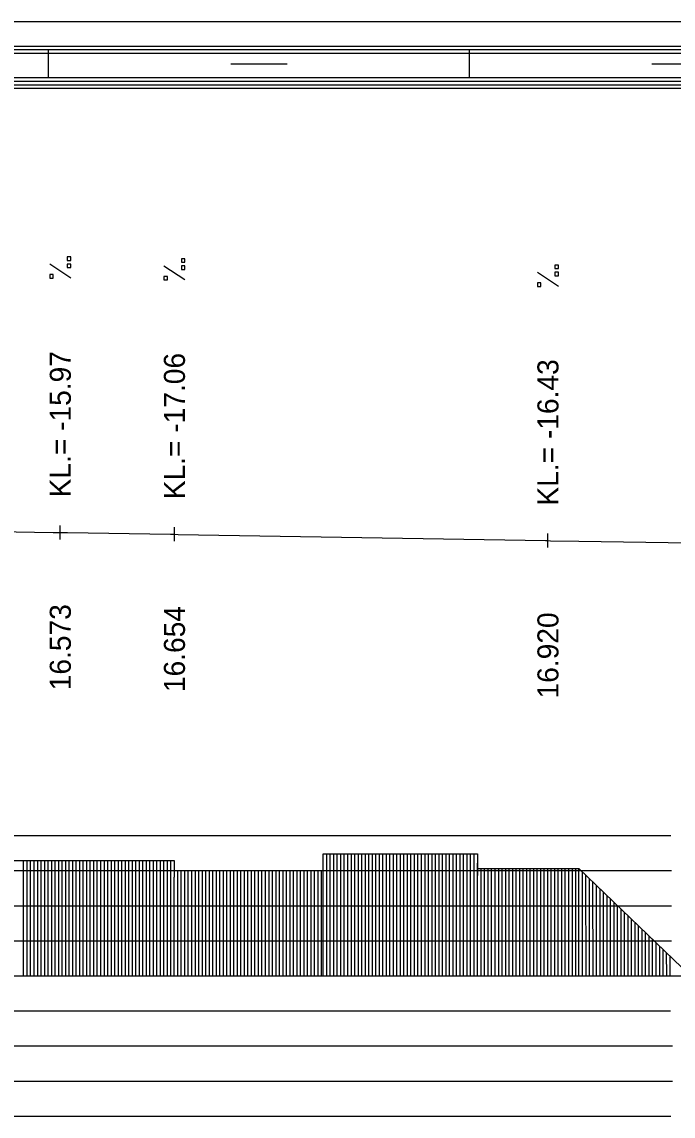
# Model space of a CAD drawing. Extents: x 2 to 10148, y 0 to 380.
# Drawn here: x 1953.1 to 1999.5, y 302 to 380 of the extents above; entities that cross this region are included whole.
import ezdxf

# ---------------------------------------------------------------- set-up
doc = ezdxf.new("R2010")
doc.units = 0
for name, color, linetype in [('NIVELETA_CARA', 7, 'Continuous'), ('NIVELETA_TEXT', 7, 'Continuous'), ('RAM', 7, 'Continuous'), ('ZRYCHL_CARA_C', 7, 'Continuous'), ('ZRYCHL_RASTR', 7, 'Continuous')]:
    doc.layers.add(name, color=color, linetype=linetype)

msp = doc.modelspace()

# ---------------------------------------------------------------- linework, layer by layer
at = {"layer": 'NIVELETA_CARA'}
for p, q in [((1955.842, 343.106), (1955.842, 344.106)), ((1947.82, 343.717), (1955.324, 343.613)), ((1955.324, 343.613), (1955.842, 343.606)), ((1955.842, 343.606), (1956.36, 343.598)), ((1956.36, 343.598), (1963.704, 343.48)), ((1963.704, 343.48), (1963.976, 343.476)), ((1963.976, 342.976), (1963.976, 343.976)), ((1963.976, 343.476), (1964.249, 343.471)), ((1964.249, 343.471), (1990.419, 343.025)), ((1990.593, 342.522), (1990.593, 343.522)), ((1990.419, 343.025), (1990.593, 343.022)), ((1990.593, 343.022), (1990.768, 343.019)), ((1990.768, 343.019), (1992.806, 342.986)), ((1992.806, 342.986), (2000.759, 342.856))]:
    msp.add_line(p, q, dxfattribs=at)
at = {"layer": 'NIVELETA_TEXT'}
for p, q in [((1956.589, 361.733), (1955.095, 362.724)), ((1956.59, 363.249), (1956.342, 363.249)), ((1956.342, 363.249), (1956.342, 363.006)), ((1956.342, 363.006), (1956.347, 363.002)), ((1956.342, 363.002), (1956.59, 363.002)), ((1956.59, 362.738), (1956.342, 362.738)), ((1956.342, 362.738), (1956.342, 362.495)), ((1956.59, 363.002), (1956.59, 363.249)), ((1956.59, 362.49), (1956.59, 362.738)), ((1964.724, 363.119), (1964.477, 363.119)), ((1964.477, 363.119), (1964.477, 362.876)), ((1964.477, 362.876), (1964.482, 362.872)), ((1964.477, 362.872), (1964.724, 362.872)), ((1964.724, 362.872), (1964.724, 363.119)), ((1955.342, 361.981), (1955.095, 361.981)), ((1955.095, 361.981), (1955.095, 361.738)), ((1955.342, 361.733), (1955.342, 361.981)), ((1956.342, 362.495), (1956.347, 362.49)), ((1956.342, 362.49), (1956.59, 362.49)), ((1964.723, 361.603), (1963.229, 362.594)), ((1964.724, 362.608), (1964.477, 362.608)), ((1964.477, 362.608), (1964.477, 362.365)), ((1964.477, 362.365), (1964.482, 362.36)), ((1964.477, 362.36), (1964.724, 362.36)), ((1964.724, 362.36), (1964.724, 362.608)), ((1991.34, 361.149), (1989.846, 362.14)), ((1991.341, 362.665), (1991.094, 362.665)), ((1991.094, 362.665), (1991.094, 362.422)), ((1991.094, 362.422), (1991.099, 362.418)), ((1991.094, 362.418), (1991.341, 362.418)), ((1991.341, 362.154), (1991.094, 362.154)), ((1991.094, 362.154), (1991.094, 361.911)), ((1991.341, 362.418), (1991.341, 362.665)), ((1991.341, 361.906), (1991.341, 362.154)), ((1955.095, 361.738), (1955.1, 361.733)), ((1955.095, 361.733), (1955.342, 361.733)), ((1963.477, 361.851), (1963.229, 361.851)), ((1963.229, 361.851), (1963.229, 361.608)), ((1963.229, 361.608), (1963.234, 361.603)), ((1963.229, 361.603), (1963.477, 361.603)), ((1963.477, 361.603), (1963.477, 361.851)), ((1990.094, 361.397), (1989.846, 361.397)), ((1989.846, 361.397), (1989.846, 361.154)), ((1989.846, 361.154), (1989.851, 361.149)), ((1989.846, 361.149), (1990.094, 361.149)), ((1990.094, 361.149), (1990.094, 361.397)), ((1991.094, 361.911), (1991.099, 361.906)), ((1991.094, 361.906), (1991.341, 361.906))]:
    msp.add_line(p, q, dxfattribs=at)
at = {"layer": 'RAM'}
for p, q in [((2170.827, 380), (1850.83, 380)), ((2170.827, 378.25), (1850.83, 378.25)), ((2170.827, 378), (1850.83, 378)), ((2170.827, 377.75), (1850.83, 377.75)), ((1955, 376), (1955, 378)), ((1985, 376), (1985, 378)), ((1968, 377), (1972, 377)), ((1998, 377), (2002, 377)), ((2170.827, 376), (1850.83, 376)), ((2170.827, 375.75), (1850.83, 375.75)), ((2170.827, 375.5), (1850.83, 375.5)), ((2170.827, 375.25), (1850.83, 375.25))]:
    msp.add_line(p, q, dxfattribs=at)
at = {"layer": 'ZRYCHL_CARA_C'}
for p, q in [((1974.583, 319.022), (1974.583, 320.69)), ((1974.583, 320.69), (1985.583, 320.69)), ((1974.833, 312), (1974.833, 320.69)), ((1975.083, 312), (1975.083, 320.69)), ((1975.333, 312), (1975.333, 320.69)), ((1975.583, 312), (1975.583, 320.69)), ((1975.833, 312), (1975.833, 320.69)), ((1976.083, 312), (1976.083, 320.69)), ((1976.333, 312), (1976.333, 320.69)), ((1976.583, 312), (1976.583, 320.69)), ((1976.833, 312), (1976.833, 320.69)), ((1977.083, 312), (1977.083, 320.69)), ((1977.333, 312), (1977.333, 320.69)), ((1977.583, 312), (1977.583, 320.69)), ((1977.833, 312), (1977.833, 320.69)), ((1978.083, 312), (1978.083, 320.69)), ((1978.333, 312), (1978.333, 320.69)), ((1978.583, 312), (1978.583, 320.69)), ((1978.833, 312), (1978.833, 320.69)), ((1979.083, 312), (1979.083, 320.69)), ((1979.333, 312), (1979.333, 320.69)), ((1979.583, 312), (1979.583, 320.69)), ((1979.833, 312), (1979.833, 320.69)), ((1980.083, 312), (1980.083, 320.69)), ((1980.333, 312), (1980.333, 320.69)), ((1980.583, 312), (1980.583, 320.69)), ((1980.833, 312), (1980.833, 320.69)), ((1981.083, 312), (1981.083, 320.69)), ((1981.333, 312), (1981.333, 320.69)), ((1981.583, 312), (1981.583, 320.69)), ((1981.833, 312), (1981.833, 320.69)), ((1982.083, 312), (1982.083, 320.69)), ((1982.333, 312), (1982.333, 320.69)), ((1982.583, 312), (1982.583, 320.69)), ((1982.833, 312), (1982.833, 320.69)), ((1983.083, 312), (1983.083, 320.69)), ((1983.333, 312), (1983.333, 320.69)), ((1983.583, 312), (1983.583, 320.69)), ((1983.833, 312), (1983.833, 320.69)), ((1984.083, 312), (1984.083, 320.69)), ((1984.333, 312), (1984.333, 320.69)), ((1984.583, 312), (1984.583, 320.69)), ((1984.833, 312), (1984.833, 320.69)), ((1985.083, 312), (1985.083, 320.69)), ((1985.333, 312), (1985.333, 320.69)), ((1985.583, 320.69), (1985.583, 319.149)), ((1942.23, 320.223), (1963.965, 320.223)), ((1953.23, 312), (1953.23, 320.223)), ((1953.48, 312), (1953.48, 320.223)), ((1953.73, 312), (1953.73, 320.223)), ((1953.98, 312), (1953.98, 320.223)), ((1954.23, 312), (1954.23, 320.223)), ((1954.48, 312), (1954.48, 320.223)), ((1954.73, 312), (1954.73, 320.223)), ((1954.98, 312), (1954.98, 320.223)), ((1955.23, 312), (1955.23, 320.223)), ((1955.48, 312), (1955.48, 320.223)), ((1955.73, 312), (1955.73, 320.223)), ((1955.98, 312), (1955.98, 320.223)), ((1956.23, 312), (1956.23, 320.223)), ((1956.48, 312), (1956.48, 320.223)), ((1956.73, 312), (1956.73, 320.223)), ((1956.98, 312), (1956.98, 320.223)), ((1957.23, 312), (1957.23, 320.223)), ((1957.48, 312), (1957.48, 320.223)), ((1957.73, 312), (1957.73, 320.223)), ((1957.98, 312), (1957.98, 320.223)), ((1958.23, 312), (1958.23, 320.223)), ((1958.48, 312), (1958.48, 320.223)), ((1958.73, 312), (1958.73, 320.223)), ((1958.98, 312), (1958.98, 320.223)), ((1959.23, 312), (1959.23, 320.223)), ((1959.48, 312), (1959.48, 320.223)), ((1959.73, 312), (1959.73, 320.223)), ((1959.98, 312), (1959.98, 320.223)), ((1960.23, 312), (1960.23, 320.223)), ((1960.48, 312), (1960.48, 320.223)), ((1960.73, 312), (1960.73, 320.223)), ((1960.98, 312), (1960.98, 320.223)), ((1961.23, 312), (1961.23, 320.223)), ((1961.48, 312), (1961.48, 320.223)), ((1961.73, 312), (1961.73, 320.223)), ((1961.98, 312), (1961.98, 320.223)), ((1962.23, 312), (1962.23, 320.223)), ((1962.48, 312), (1962.48, 320.223)), ((1962.73, 312), (1962.73, 320.223)), ((1962.98, 312), (1962.98, 320.223)), ((1963.23, 312), (1963.23, 320.223)), ((1963.48, 312), (1963.48, 320.223)), ((1963.73, 312), (1963.73, 320.223)), ((1963.965, 320.223), (1963.965, 319.022)), ((1974.583, 312), (1974.583, 320.028)), ((1985.583, 312), (1985.583, 320.028)), ((1963.965, 319.5), (1974.583, 319.5)), ((1963.965, 312), (1963.965, 319.022)), ((1964.215, 312), (1964.215, 319.5)), ((1964.465, 312), (1964.465, 319.5)), ((1964.715, 312), (1964.715, 319.5)), ((1964.965, 312), (1964.965, 319.5)), ((1965.215, 312), (1965.215, 319.5)), ((1965.465, 312), (1965.465, 319.5)), ((1965.715, 312), (1965.715, 319.5)), ((1965.965, 312), (1965.965, 319.5)), ((1966.215, 312), (1966.215, 319.5)), ((1966.465, 312), (1966.465, 319.5)), ((1966.715, 312), (1966.715, 319.5)), ((1966.965, 312), (1966.965, 319.5)), ((1967.215, 312), (1967.215, 319.5)), ((1967.465, 312), (1967.465, 319.5)), ((1967.715, 312), (1967.715, 319.5)), ((1967.965, 312), (1967.965, 319.5)), ((1968.215, 312), (1968.215, 319.5)), ((1968.465, 312), (1968.465, 319.5)), ((1968.715, 312), (1968.715, 319.5)), ((1968.965, 312), (1968.965, 319.5)), ((1969.215, 312), (1969.215, 319.5)), ((1969.465, 312), (1969.465, 319.5)), ((1969.715, 312), (1969.715, 319.5)), ((1969.965, 312), (1969.965, 319.5)), ((1970.215, 312), (1970.215, 319.5)), ((1970.465, 312), (1970.465, 319.5)), ((1970.715, 312), (1970.715, 319.5)), ((1970.965, 312), (1970.965, 319.5)), ((1971.215, 312), (1971.215, 319.5)), ((1971.465, 312), (1971.465, 319.5)), ((1971.715, 312), (1971.715, 319.5)), ((1971.965, 312), (1971.965, 319.5)), ((1972.215, 312), (1972.215, 319.5)), ((1972.465, 312), (1972.465, 319.5)), ((1972.715, 312), (1972.715, 319.5)), ((1972.965, 312), (1972.965, 319.5)), ((1973.215, 312), (1973.215, 319.5)), ((1973.465, 312), (1973.465, 319.5)), ((1973.715, 312), (1973.715, 319.5)), ((1973.965, 312), (1973.965, 319.5)), ((1974.215, 312), (1974.215, 319.5)), ((1974.465, 312), (1974.465, 319.5)), ((1985.578, 319.646), (1992.806, 319.646)), ((1985.583, 312), (1985.583, 319.149)), ((1985.833, 312), (1985.833, 319.646)), ((1986.083, 312), (1986.083, 319.646)), ((1986.333, 312), (1986.333, 319.646)), ((1986.583, 312), (1986.583, 319.646)), ((1986.833, 312), (1986.833, 319.646)), ((1987.083, 312), (1987.083, 319.646)), ((1987.333, 312), (1987.333, 319.646)), ((1987.583, 312), (1987.583, 319.646)), ((1987.833, 312), (1987.833, 319.646)), ((1988.083, 312), (1988.083, 319.646)), ((1988.333, 312), (1988.333, 319.646)), ((1988.583, 312), (1988.583, 319.646)), ((1988.833, 312), (1988.833, 319.646)), ((1989.083, 312), (1989.083, 319.646)), ((1989.333, 312), (1989.333, 319.646)), ((1989.583, 312), (1989.583, 319.646)), ((1989.833, 312), (1989.833, 319.646)), ((1990.083, 312), (1990.083, 319.646)), ((1990.333, 312), (1990.333, 319.646)), ((1990.583, 312), (1990.583, 319.646)), ((1990.833, 312), (1990.833, 319.646)), ((1991.083, 312), (1991.083, 319.646)), ((1991.333, 312), (1991.333, 319.646)), ((1991.583, 312), (1991.583, 319.646)), ((1991.833, 312), (1991.833, 319.646)), ((1992.083, 312), (1992.083, 319.646)), ((1992.333, 312), (1992.333, 319.646)), ((1992.583, 312), (1992.583, 319.646)), ((1992.806, 312), (1992.806, 319.646)), ((1992.806, 319.645), (2000.759, 312)), ((1993.056, 312), (1993.055, 319.406)), ((1993.306, 312), (1993.303, 319.168)), ((1993.556, 312), (1993.554, 318.927)), ((1993.806, 312), (1993.804, 318.686)), ((1994.056, 312), (1994.058, 318.442)), ((1994.306, 312), (1994.307, 318.199)), ((1994.556, 312), (1994.555, 317.961)), ((1994.806, 312), (1994.804, 317.721)), ((1995.056, 312), (1995.056, 317.479)), ((1995.306, 312), (1995.305, 317.24)), ((1995.556, 312), (1995.557, 316.998)), ((1995.806, 312), (1995.806, 316.759)), ((1996.056, 312), (1996.058, 316.517)), ((1996.306, 312), (1996.306, 316.279)), ((1996.556, 312), (1996.557, 316.037)), ((1996.806, 312), (1996.806, 315.798)), ((1997.056, 312), (1997.056, 315.557)), ((1997.306, 312), (1997.306, 315.318)), ((1997.556, 312), (1997.556, 315.077)), ((1997.806, 312), (1997.806, 314.837)), ((1998.056, 312), (1998.055, 314.597)), ((1998.306, 312), (1998.305, 314.358)), ((1998.556, 312), (1998.556, 314.116)), ((1998.806, 312), (1998.806, 313.89)), ((1999.056, 312), (1999.052, 313.64)), ((1999.306, 312), (1999.299, 313.402)), ((1850.83, 312), (2170.827, 312))]:
    msp.add_line(p, q, dxfattribs=at)
at = {"layer": 'ZRYCHL_RASTR'}
for p, q in [((1791.352, 322), (1999.35, 322)), ((1791.275, 319.5), (1999.407, 319.5)), ((1791.198, 317), (1999.393, 317)), ((1791.198, 314.5), (1999.393, 314.5)), ((1791.275, 309.5), (1999.321, 309.5)), ((1791.198, 307), (1999.472, 307)), ((1791.121, 304.5), (1999.472, 304.5)), ((1791.121, 302), (1999.34, 302))]:
    msp.add_line(p, q, dxfattribs=at)

# ---------------------------------------------------------------- texts
at = {"layer": 'NIVELETA_TEXT'}
for s, p in [('KL.= -15.97', (1956.592, 346.106)), ('KL.= -17.06', (1964.726, 345.976)), ('KL.= -16.43', (1991.343, 345.522)), ('16.573', (1956.592, 332.356)), ('16.654', (1964.726, 332.226)), ('16.920', (1991.343, 331.772))]:
    msp.add_text(s, height=1.5, rotation=90, dxfattribs=at).set_placement(p)

doc.saveas('drawing.dxf')
